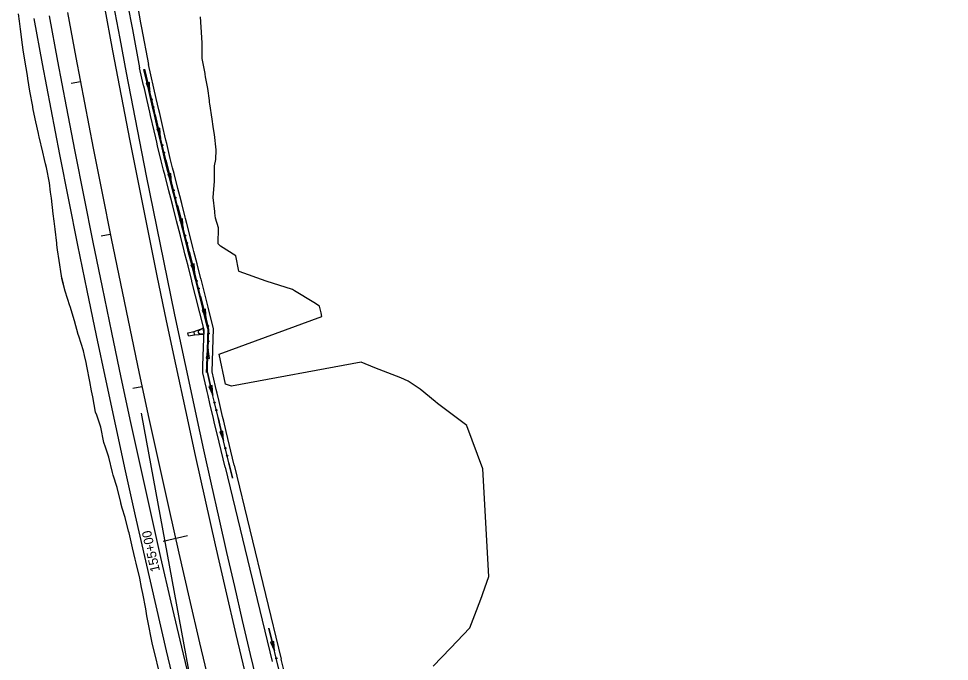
# Model space of a CAD drawing. Extents: x 948761 to 996004, y 1858548 to 1925175.
# Drawn here: x 986402 to 987000, y 1872573 to 1872986 of the extents above; entities that cross this region are included whole.
import ezdxf

# ---------------------------------------------------------------- set-up
doc = ezdxf.new("R2010")
doc.units = 0
for name, color, linetype in [('62', 7, 'Continuous'), ('R_Drainage', 7, 'Continuous'), ('R_Horz Alg', 7, 'Continuous'), ('R_Horz Alg Annot', 7, 'Continuous'), ('R_Proposed Const Limits', 7, 'Continuous'), ('R_Proposed Road', 7, 'Continuous')]:
    doc.layers.add(name, color=color, linetype=linetype)

msp = doc.modelspace()

# ---------------------------------------------------------------- linework, layer by layer
at = {"layer": '62'}
for p, q in [((986486.09, 1872945.09), (986484.03, 1872944.61)), ((986484.03, 1872944.61), (986486.44, 1872939.01)), ((986486.44, 1872939.01), (986486.09, 1872945.09)), ((986492.86, 1872915.82), (986490.8, 1872915.35)), ((986490.8, 1872915.35), (986493.18, 1872909.74)), ((986493.18, 1872909.74), (986492.86, 1872915.82)), ((986499.87, 1872886.64), (986497.82, 1872886.11)), ((986497.82, 1872886.11), (986500.33, 1872880.57)), ((986500.33, 1872880.57), (986499.87, 1872886.64)), ((986507.36, 1872857.55), (986505.31, 1872857.03)), ((986505.31, 1872857.03), (986507.82, 1872851.48)), ((986507.82, 1872851.48), (986507.36, 1872857.55)), ((986514.73, 1872828.43), (986512.68, 1872827.91)), ((986512.68, 1872827.91), (986515.19, 1872822.36)), ((986515.19, 1872822.36), (986514.73, 1872828.43)), ((986522.11, 1872799.31), (986520.06, 1872798.79)), ((986520.06, 1872798.79), (986522.55, 1872793.23)), ((986522.55, 1872793.23), (986522.11, 1872799.31)), ((986523.81, 1872773.72), (986522.54, 1872767.76)), ((986524.66, 1872767.69), (986523.81, 1872773.72)), ((986522.54, 1872767.76), (986524.66, 1872767.69)), ((986526.41, 1872750.21), (986524.35, 1872749.73)), ((986524.35, 1872749.73), (986526.76, 1872744.13)), ((986526.76, 1872744.13), (986526.41, 1872750.21)), ((986533.33, 1872720.98), (986531.28, 1872720.49)), ((986531.28, 1872720.49), (986533.69, 1872714.9)), ((986533.69, 1872714.9), (986533.33, 1872720.98)), ((986534.71, 1872697.68), (986564.95, 1872572.89)), ((986540.54, 1872699.08), (986570.77, 1872574.32)), ((986566, 1872585.78), (986563.95, 1872585.28)), ((986563.95, 1872585.28), (986566.4, 1872579.7)), ((986566.4, 1872579.7), (986566, 1872585.78))]:
    msp.add_line(p, q, dxfattribs=at)
for points in [[(986461.78, 1873051.16), (986465.41, 1873031.49), (986467.22, 1873021.66), (986470.85, 1873001.99), (986471.72, 1872997.26), (986472.66, 1872992.18), (986474.48, 1872982.39), (986475.1, 1872979.1), (986479.68, 1872954.59)], [(986467.68, 1873052.25), (986467.68, 1873052.25), (986471.31, 1873032.58), (986473.12, 1873022.74), (986476.75, 1873003.08), (986477.62, 1872998.35), (986478.56, 1872993.27), (986480.38, 1872983.49), (986480.99, 1872980.2), (986485.38, 1872956.74)], [(986521.25, 1872786.05), (986515.78, 1872807.85), (986513.43, 1872817.12), (986513.33, 1872817.49), (986510.87, 1872827.14), (986508.87, 1872835.03), (986508.43, 1872836.79), (986505.99, 1872846.44), (986504.35, 1872852.94), (986503.55, 1872856.08), (986503.28, 1872857.09), (986501.05, 1872865.72), (986499.73, 1872870.83), (986498.57, 1872875.38), (986496.09, 1872885.03), (986495.14, 1872888.74), (986493.62, 1872894.71), (986491.33, 1872904.43), (986490.79, 1872906.77), (986490.16, 1872909.47), (986489.09, 1872914.14), (986486.84, 1872923.84), (986486.32, 1872926.11), (986484.62, 1872933.54), (986482.84, 1872941.21), (986482.47, 1872942.76), (986482.36, 1872943.23), (986479.68, 1872954.59)], [(986523.79, 1872786.28), (986523.05, 1872789.18), (986520.62, 1872798.83), (986520.37, 1872799.85), (986518.2, 1872808.48), (986515.85, 1872817.76), (986515.75, 1872818.13), (986513.29, 1872827.77), (986511.29, 1872835.66), (986510.84, 1872837.42), (986508.41, 1872847.08), (986506.77, 1872853.58), (986505.96, 1872856.73), (986505.7, 1872857.74), (986503.46, 1872866.37), (986502.15, 1872871.48), (986500.98, 1872876.02), (986498.51, 1872885.67), (986497.56, 1872889.39), (986496.04, 1872895.33), (986493.76, 1872905.02), (986493.22, 1872907.35), (986492.59, 1872910.05), (986492.59, 1872910.05), (986491.52, 1872914.72), (986489.27, 1872924.42), (986489.06, 1872925.35), (986488.76, 1872926.68), (986487.05, 1872934.12), (986485.27, 1872941.8), (986484.9, 1872943.35), (986484.79, 1872943.82), (986482.5, 1872953.52)], [(986524.28, 1872786.39), (986523.54, 1872789.28), (986521.11, 1872798.93), (986520.86, 1872799.95), (986518.69, 1872808.58), (986516.34, 1872817.86), (986516.24, 1872818.23), (986513.78, 1872827.87), (986511.78, 1872835.76), (986511.33, 1872837.52), (986508.9, 1872847.18), (986507.26, 1872853.68), (986506.45, 1872856.83), (986506.19, 1872857.84), (986503.95, 1872866.47), (986502.64, 1872871.57), (986501.47, 1872876.12), (986499, 1872885.77), (986498.05, 1872889.48), (986496.53, 1872895.42), (986494.25, 1872905.11), (986493.71, 1872907.45), (986493.09, 1872910.15), (986493.08, 1872910.15), (986492.01, 1872914.81), (986489.77, 1872924.51), (986489.55, 1872925.45), (986489.25, 1872926.78), (986487.54, 1872934.22), (986485.76, 1872941.9), (986485.39, 1872943.45), (986485.28, 1872943.91), (986482.99, 1872953.61)], [(986482.99, 1872953.61), (986485.28, 1872943.91), (986485.39, 1872943.45), (986485.76, 1872941.9), (986486.43, 1872939.01)], [(986527.22, 1872786.97), (986524.02, 1872799.66), (986523.77, 1872800.68), (986521.6, 1872809.32), (986519.24, 1872818.6), (986519.15, 1872818.97), (986516.69, 1872828.61), (986514.69, 1872836.5), (986514.24, 1872838.26), (986511.8, 1872847.91), (986510.17, 1872854.42), (986509.36, 1872857.58), (986509.09, 1872858.59), (986506.86, 1872867.22), (986505.54, 1872872.32), (986504.38, 1872876.87), (986501.9, 1872886.51), (986500.95, 1872890.23), (986499.44, 1872896.14), (986497.17, 1872905.8), (986496.63, 1872908.12), (986496.01, 1872910.82), (986496.01, 1872910.82), (986494.93, 1872915.49), (986492.69, 1872925.19), (986492.17, 1872927.45), (986490.47, 1872934.89), (986485.38, 1872956.74)], [(986489.79, 1872924.39), (986489.8, 1872924.35)], [(986489.8, 1872924.35), (986492.01, 1872914.81), (986493.08, 1872910.15), (986493.09, 1872910.15), (986493.18, 1872909.74)], [(986496.6, 1872895.13), (986496.61, 1872895.1)], [(986496.61, 1872895.1), (986498.05, 1872889.48), (986499, 1872885.77), (986500.33, 1872880.57)], [(986504.07, 1872866.04), (986504.08, 1872866)], [(986504.08, 1872866), (986506.19, 1872857.84), (986506.45, 1872856.83), (986507.26, 1872853.68), (986507.81, 1872851.47)], [(986511.48, 1872836.93), (986511.49, 1872836.89)], [(986511.49, 1872836.89), (986511.78, 1872835.76), (986513.78, 1872827.87), (986515.19, 1872822.36)], [(986518.88, 1872807.82), (986518.89, 1872807.78)], [(986518.89, 1872807.78), (986520.86, 1872799.95), (986521.11, 1872798.93), (986522.55, 1872793.23)], [(986520.31, 1872758.43), (986520.45, 1872762.86), (986520.65, 1872769.07), (986521.25, 1872786.05)], [(986522.83, 1872758.62), (986522.96, 1872762.67), (986523.16, 1872768.87), (986523.52, 1872779.11), (986523.61, 1872781.68), (986523.79, 1872786.28)], [(986523.32, 1872758.73), (986523.45, 1872762.77), (986523.65, 1872768.97), (986524.01, 1872779.22), (986524.1, 1872781.78), (986524.28, 1872786.39)], [(986526.33, 1872759.04), (986527.22, 1872786.97)], [(986523.32, 1872758.73), (986523.45, 1872762.77), (986523.65, 1872768.97), (986523.81, 1872773.72)], [(986534.71, 1872697.68), (986529.56, 1872719.3), (986528, 1872725.91), (986527.27, 1872728.98), (986524.97, 1872738.67), (986523.73, 1872743.88), (986523.13, 1872746.44), (986522.68, 1872748.35), (986520.31, 1872758.43)], [(986539.49, 1872690.68), (986539.42, 1872690.96), (986537.1, 1872700.64), (986535.19, 1872708.64), (986534.79, 1872710.31), (986532.48, 1872719.99), (986530.92, 1872726.61), (986530.19, 1872729.68), (986527.89, 1872739.36), (986526.65, 1872744.57), (986526.05, 1872747.13), (986525.6, 1872749.04), (986523.32, 1872758.73)], [(986523.32, 1872758.73), (986525.6, 1872749.04), (986526.05, 1872747.13), (986526.65, 1872744.57), (986526.76, 1872744.13)], [(986540.54, 1872699.08), (986535.4, 1872720.69), (986533.84, 1872727.3), (986533.11, 1872730.37), (986530.81, 1872740.05), (986529.57, 1872745.26), (986528.97, 1872747.82), (986528.52, 1872749.73), (986526.33, 1872759.04)], [(986530.22, 1872729.53), (986530.23, 1872729.5)], [(986530.23, 1872729.5), (986530.92, 1872726.61), (986532.48, 1872719.99), (986533.69, 1872714.9)], [(986537.18, 1872700.31), (986537.19, 1872700.28)], [(986537.19, 1872700.28), (986539.42, 1872690.96), (986539.49, 1872690.68)], [(986569.93, 1872565.28), (986567.56, 1872574.94), (986565.59, 1872583.03), (986565.2, 1872584.61), (986562.85, 1872594.27)], [(986562.85, 1872594.27), (986565.2, 1872584.61), (986565.59, 1872583.03), (986566.4, 1872579.7)], [(986575.23, 1872556.35), (986570.77, 1872574.32)]]:
    msp.add_lwpolyline(points, dxfattribs=at)
for centre in [(986487.6, 1872934.14), (986488.72, 1872929.26), (986494.34, 1872904.87), (986495.49, 1872899.99), (986501.61, 1872875.73), (986502.86, 1872870.87), (986509.07, 1872846.63), (986510.3, 1872841.77), (986516.46, 1872817.51), (986517.69, 1872812.66), (986523.81, 1872788.39), (986523.95, 1872778.73), (986524.14, 1872783.73), (986527.95, 1872739.27), (986529.1, 1872734.39), (986534.89, 1872710.04), (986536.05, 1872705.17), (986567.62, 1872574.84)]:
    msp.add_circle(centre, 0.375, dxfattribs=at)
at = {"layer": 'R_Drainage'}
for p, q in [((986514.74, 1872784.93), (986520.52, 1872787.17)), ((986520.52, 1872787.17), (986517.96, 1872785.72)), ((986521.34, 1872783.25), (986520.52, 1872787.17)), ((986510.82, 1872784.1), (986514.74, 1872784.93)), ((986511.24, 1872782.14), (986510.82, 1872784.1)), ((986511.24, 1872782.14), (986515.15, 1872782.97)), ((986515.15, 1872782.97), (986514.74, 1872784.93)), ((986515.15, 1872782.97), (986521.34, 1872783.25)), ((986521.34, 1872783.25), (986518.42, 1872783.55))]:
    msp.add_line(p, q, dxfattribs=at)
msp.add_arc((986518.53, 1872784.7), 1.17, 119.41975, 264.3599, dxfattribs=at)
at = {"layer": 'R_Horz Alg'}
msp.add_arc((994885.09, 1874549.52), 8594.37, 190.453455, 203.072581, dxfattribs=at)
at = {"layer": 'R_Horz Alg Annot'}
msp.add_line((986605.79, 1872055.68), (986480.9, 1872732.56), dxfattribs=at)
for points in [[(986435.79, 1872944.64), (986441.69, 1872945.76)], [(986455.04, 1872846.44), (986460.92, 1872847.63)], [(986475.42, 1872748.47), (986481.29, 1872749.73)], [(986495, 1872650.3), (986510.6, 1872653.84)]]:
    msp.add_lwpolyline(points, dxfattribs=at)
at = {"layer": 'R_Proposed Const Limits'}
for points in [[(986492.15, 1872567.35), (986489.72, 1872577.09), (986488.12, 1872583.85), (986487.51, 1872586.88), (986485.56, 1872596.73), (986484.49, 1872602.13), (986483.66, 1872606.59), (986481.76, 1872616.45), (986480.99, 1872620.43), (986479.88, 1872626.31), (986477.58, 1872636.07), (986476.94, 1872638.6), (986475.13, 1872645.81), (986472.97, 1872655.6), (986472.7, 1872656.73), (986470.58, 1872665.35), (986468.49, 1872671.52), (986467.69, 1872674.69), (986467.62, 1872674.97), (986465.33, 1872684.74), (986462.68, 1872692.66), (986462.29, 1872694.34), (986460.02, 1872704.12), (986457.73, 1872710.64), (986456.81, 1872713.69), (986454.82, 1872723.53), (986453.18, 1872728.71), (986452.19, 1872731.21), (986451.45, 1872733.07), (986449.62, 1872742.95), (986448.89, 1872746.84), (986447.78, 1872752.82), (986445.94, 1872762.69), (986445.4, 1872765.14), (986444.42, 1872769.55), (986443.77, 1872772.49), (986440.62, 1872782.08), (986440.29, 1872783.1), (986437.96, 1872791.78), (986435.08, 1872801.04), (986434.96, 1872801.41), (986431.87, 1872811.03), (986430, 1872819.02), (986429.63, 1872820.82), (986428.04, 1872830.74), (986427, 1872837.43), (986426.61, 1872840.7), (986426.5, 1872841.75), (986425.58, 1872850.73), (986424.8, 1872855.99), (986424.26, 1872860.71), (986423.19, 1872870.73), (986422.58, 1872874.55), (986421.81, 1872880.69), (986419.98, 1872890.56), (986419.36, 1872892.9), (986418.66, 1872895.61), (986418.66, 1872895.61), (986417.54, 1872900.31), (986415.25, 1872910.09), (986415.04, 1872911.03), (986414.74, 1872912.38), (986413.09, 1872919.9), (986411.44, 1872927.68), (986411.14, 1872929.25), (986411.04, 1872929.73), (986409.21, 1872939.59), (986407.97, 1872947.61), (986407.67, 1872949.52), (986405.94, 1872959.41), (986404.98, 1872966.01), (986404.56, 1872969.36), (986403.3, 1872979.34), (986402.55, 1872984.5), (986401.99, 1872989.28)], [(986520.01, 1872960.64), (986519.97, 1872968.78), (986519.93, 1872970.71), (986519.23, 1872980.65), (986518.96, 1872987.29)], [(986700.4, 1872696.8), (986690.19, 1872724.25), (986690.05, 1872724.5), (986679.78, 1872732.24), (986671.31, 1872738.65), (986669.64, 1872740.02), (986660.03, 1872747.93), (986652.46, 1872753.13), (986647.75, 1872755.28), (986631.06, 1872761.7), (986622.14, 1872765.19), (986538.9, 1872749.9), (986535.06, 1872751.08), (986530.94, 1872770.52), (986596.96, 1872794.66), (986596.43, 1872797.07), (986595.44, 1872801.39), (986591.71, 1872803.63), (986579.36, 1872811.12), (986578.05, 1872811.92), (986561.04, 1872817.39), (986543.69, 1872823.52), (986543.62, 1872823.89), (986541.7, 1872833.62), (986531.79, 1872839.86), (986530.18, 1872841.38), (986530.49, 1872851.56), (986528.46, 1872857.97), (986528.12, 1872861.21), (986528.01, 1872862.25), (986527.06, 1872871.11), (986527.38, 1872876.53), (986527.9, 1872881.4), (986527.97, 1872891.52), (986528.69, 1872895.55), (986529.02, 1872901.83), (986527.89, 1872911.71), (986527.51, 1872914.06), (986527, 1872916.77), (986527, 1872916.77), (986526.38, 1872921.51), (986524.87, 1872931.31), (986524.76, 1872932.26), (986524.59, 1872933.61), (986523.61, 1872941.16), (986522.1, 1872948.85), (986521.9, 1872950.43), (986521.84, 1872950.9), (986520.01, 1872960.64)], [(986431.87, 1872811.03), (986429.87, 1872819), (986429.55, 1872820.8)], [(986668.5, 1872569.85), (986679.55, 1872581.35), (986687.86, 1872590.11), (986691.83, 1872594.18), (986692.13, 1872594.44), (986696.37, 1872605.52), (986699.64, 1872614.72), (986700.28, 1872616.51), (986704.19, 1872627.48), (986700.4, 1872696.8)]]:
    msp.add_lwpolyline(points, dxfattribs=at)
at = {"layer": 'R_Proposed Road'}
for radius, end in [(8570.37, 203.072581), (8564.37, 200.088068), (8616.37, 203.072581), (8606.37, 203.072581)]:
    msp.add_arc((994885.09, 1874549.52), radius, 190.453455, end, dxfattribs=at)

# ---------------------------------------------------------------- texts
at = {"layer": 'R_Horz Alg Annot'}
msp.add_text('155+00', height=6, rotation=102.75473, dxfattribs=at).set_placement((986492.9, 1872631.17))

doc.saveas('drawing.dxf')
